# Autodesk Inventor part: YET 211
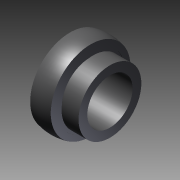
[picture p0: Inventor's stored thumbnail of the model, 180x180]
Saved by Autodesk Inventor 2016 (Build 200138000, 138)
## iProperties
Category: PARTsolutions
Company: SKF
Created: 2016-10
Part Number: YET 211
Catalog Web Link: www.cadenas.de
Description: Y-bearings, series YET 2 /W64-Insert bearings
Vendor: SKF
Document SubType Name: Modeling
Designer: psAdmin
Manufacturer: SKF
Mass: 180.057 g
Surface Area: 337.496 cm^2
Volume: 180.057 cm^3
Density: 1 g/cm^3
Material: Generic
Appearance: PSOLRGB-175-175-175
PSOL_IDENT_0: {$CADENAS_DATA\23d-libs\skf\skf_ps\bearing_units\bearings\ybrg2_bu.prj},182 {VTYP=3D},{NB=YET 211 },
PSOL_IDENT_1: {LINA=YET 211 },{NN=Y-bearings, series YET 2 /W64},{DATE=12.09.2016 08:57:20},{GEOMDATE=20.11.2014 0
PSOL_IDENT_2: 9:34:00},{VERSION=},{LINEID=240},{LINESUBID=-1},{WBVAR=}  {NB=YET 211 },{LINA=YET 211 },{KT=DUMMY},{
PSOL_IDENT_3: PRODUCTID=103011211},{DESIGNATION=YET 211},{D=55.0000},{E=-1000000015047466219876688855040.0000},{F=
PSOL_IDENT_4: 100.000},{G=-1000000015047466219876688855040.000},{H=-1000000015047466219876688855040.000},{I=48.400
PSOL_IDENT_5: },{J=32.550},{K=20.600},{L=-1000000015047466219876688855040.000},{M=-1000000015047466219876688855040
PSOL_IDENT_6: .000},{N=-1000000015047466219876688855040.000},{O=25.000},{P=5.500},{Q=-1000000015047466219876688855
PSOL_IDENT_7: 040.000},{R=-1000000015047466219876688855040.000},{S=-1000000015047466219876688855040.000},{T=69.100
PSOL_IDENT_8: },{U=76.200},{V=-1000000015047466219876688855040.000},{W=-1000000015047466219876688855040.000},{X=-1
PSOL_IDENT_9: 000000015047466219876688855040.000},{Y=-1000000015047466219876688855040.000},{Z=-1000000015047466219
PSOL_IDENT_10: 876688855040.000},{AA=-1000000015047466219876688855040.000},{AB=1.000},{AC=-100000001504746621987668
PSOL_IDENT_11: 8855040.000},{AD=-1000000015047466219876688855040.000},{AE=36.400},{AF=7.900},{AG=10.0000},{AH=43.60
PSOL_IDENT_12: 0},{AI=29.000},{AJ=1.250},{AK=-1000000015047466219876688855040.000},{AL=-100000001504746621987668885
PSOL_IDENT_13: 5040.000},{AM=-1000000015047466219876688855040.000},{AN=-1000000015047466219876688855040.000},{AO=-1
PSOL_IDENT_14: 000000015047466219876688855040.000},{AP=3600.000},{AQ=-1000000015047466219876688855040.000},{AR=0.90
PSOL_IDENT_15: 0},{AS=-1000000015047466219876688855040.000},{AT=-1000000015047466219876688855040.000},{AU=-10000000
PSOL_IDENT_16: 15047466219876688855040.000},{AV=-1000000015047466219876688855040.000},{AW=-100000001504746621987668
PSOL_IDENT_17: 8855040.000},{AX=-1000000015047466219876688855040.000},{AY=-1000000015047466219876688855040.000},{AZ=
PSOL_IDENT_18: -1000000015047466219876688855040.000},{BA=14.000},{BB=-1000000015047466219876688855040.000},{BC=-100
PSOL_IDENT_19: 0000015047466219876688855040.000},{BD=-1000000015047466219876688855040.000},{BE=-1000000015047466219
PSOL_IDENT_20: 876688855040.000},{BF=-1000000015047466219876688855040.000},{BG=-1000000015047466219876688855040.000
PSOL_IDENT_21: },{BH=-1000000015047466219876688855040.000},{BI=-1000000015047466219876688855040.000},{BJ=-100000001
PSOL_IDENT_22: 5047466219876688855040.000},{BK=-1000000015047466219876688855040.000},{BL=-1000000015047466219876688
PSOL_IDENT_23: 855040.000},{BM=-1000000015047466219876688855040.000},{BN=-1000000015047466219876688855040.000},{BO=
PSOL_IDENT_24: -1000000015047466219876688855040.000},{BP=77.500},{BQ=14.288},{BR=-1000000015047466219876688855040.0
PSOL_IDENT_25: 00},{BS=10.000},{BT=1.000},{BU=-1000000015047466219876688855040.000},{BV=-10000000150474662198766888
PSOL_IDENT_26: 55040.000},{BW=-1000000015047466219876688855040.000},{BX=-1000000015047466219876688855040.000},{BY=-
PSOL_IDENT_27: 1000000015047466219876688855040.000},{BZ=-1000000015047466219876688855040.000},{CA=-1000000015047466
PSOL_IDENT_28: 219876688855040.000},{CB=0.0008},{CC=16.500},{CD=-1000000015047466219876688855040.000},{CEX=-1000000
PSOL_IDENT_29: 015047466219876688855040.000},{CF=-1000000015047466219876688855040.000},{CG=-10000000150474662198766
PSOL_IDENT_30: 88855040.000},{CH=1.600},{CI=0.000},{CJ=0.000},{CK=0.000},{CL=20.000},{CM=25.000},{CN=-1000000015047
PSOL_IDENT_31: 466219876688855040.000},{CO=-1000000015047466219876688855040.000},{CP=-},{CQ=-},{CR=-100000001504746
PSOL_IDENT_32: 6219876688855040.000},{CS=-1000000015047466219876688855040.000},{CT=-1000000015047466219876688855040
PSOL_IDENT_33: .000},{CU=M 10×1},{CV=-1000000015047466219876688855040.000},{CW=5.00000},{CX=-1000000015047466219876
PSOL_IDENT_34: 688855040.000},{CY=-1000000015047466219876688855040.000},{CZ=-1000000015047466219876688855040.000},{
PSOL_IDENT_35: DA=-1000000015047466219876688855040.000},{DB=-1000000015047466219876688855040.000},{DC=-100000001504
PSOL_IDENT_36: 7466219876688855040.000},{DD=-1000000015047466219876688855040.000},{DE=-1000000015047466219876688855
PSOL_IDENT_37: 040.000},{DF=-1000000015047466219876688855040.000},{DG=-1000000015047466219876688855040.000},{DH=-10
PSOL_IDENT_38: 00000015047466219876688855040.000},{TYPEID=103011},{INFO=LINK},{B1BRG=48.4},{B2BRG=11.95},{B3BRG1=-0
PSOL_IDENT_39: .5},{B3BRG=0},{CE=25},{DM=77.5},{DW=14.288},{H1BRG=7.05},{H2BRG=10.6},{HBRG=22.5},{XOFF=0},{YI=27.5}
PSOL_IDENT_40: ,{X0WB=0},{Y0WB=38.75},{RWB=7.144},{TAXONOMY=1},{B3BRGNEW=0.5}
NN: Y-bearings, series YET 2 /W64
NT: Insert bearings
NB: YET 211
NBSYN: $DESIGNATION.
LINA: YET 211
PRODUCTID: 103011211
DESIGNATION: YET 211
D: 55.0000
F: 100.000
I: 48.400
J: 32.550
K: 20.600
O: 25.000
P: 5.500
T: 69.100
U: 76.200
AB: 1.000
AE: 36.400
AF: 7.900
AG: 10.0000
AH: 43.600
AI: 29.000
AJ: 1.250
AP: 3600.000
AR: 0.900
BA: 14.000
BP: 77.500
BQ: 14.288
BS: 10.000
BT: 1.000
CB: 0.0008
CC: 16.500
CH: 1.600
CI: 0.000
CJ: 0.000
CK: 0.000
CL: 20.000
CM: 25.000
CP: -
CQ: -
CU: M 10×1
CW: 5.00000
TYPEID: 103011
INFO: LINK
SUPPLIER: SKF
ARTICLENO: YET 211
BOMINFO: YET 211
CREATOR: CADENAS GmbH
Title: YET 211
Author: Cadenas PARTsolutions
Comments: Insert bearings
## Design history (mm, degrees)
sketch "Sketch_1"
  geometry: L1 (50, 0)-(-50, 0); L2 (-12.51, 34.55)-(-12.51, 27.5); L3 (-12.51, 27.5)-(35.89, 27.5); L4 (35.89, 27.5)-(35.89, 38.1); L5 (35.89, 38.1)-(15.29, 38.1); L6 (15.29, 38.1)-(15.29, 34.55); L7 (15.29, 34.55)-(12, 34.55); L8 (12, 34.55)-(12, 41.481); L9 (12, 41.481)-(12.5, 41.481); L10 (12.5, 41.481)-(12.5, 48.412); L11 (-12.5, 48.412)-(-12.5, 41.481); L12 (-12.5, 41.481)-(-12, 41.481); L13 (-12, 41.481)-(-12, 34.55); L14 (-12, 34.55)-(-12.51, 34.55); A1 r 50 centre (0, 0) between (12.5, 48.412) and (-12.5, 48.412)
  constraints: 28 end point, 2 point on circle, 1 centre point
revolve "Revolution1" sketch "Sketch_1" stored, may be unused: angle "d0" = 360 deg
node "brg_XY"
node "brg_YZ"
node "brg_ZX"
node "brg_X"
node "brg_Y"
node "brg_Z"
node "brg_Center"
body "Solid1"
